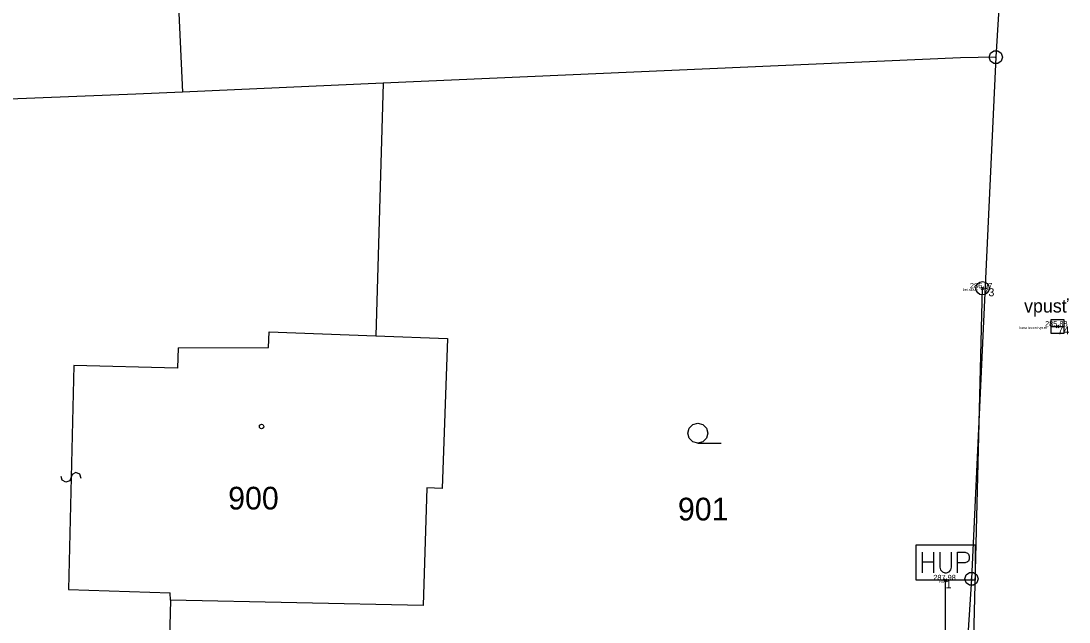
# Model space of a CAD drawing. Extents: x -456675 to -456278, y -1112395 to -1112217.
# Drawn here: x -456598.34 to -456559.06, y -1112289.23 to -1112266.7 of the extents above; entities that cross this region are included whole.
import ezdxf

# ---------------------------------------------------------------- set-up
doc = ezdxf.new("R2010")
doc.units = 0
for name, color, linetype in [('Cislo_bodu', 7, 'Continuous'), ('g_elektrina', 7, 'Continuous'), ('g_kanalizace', 7, 'Continuous'), ('g_ploty', 7, 'Continuous'), ('g_plyn', 7, 'Continuous'), ('Katastralni_mapa', 7, 'Continuous'), ('Kod_bodu', 7, 'Continuous'), ('Vyska_bodu', 7, 'Continuous'), ('Znacka_bodu', 7, 'Continuous')]:
    doc.layers.add(name, color=color, linetype=linetype)

msp = doc.modelspace()

# ---------------------------------------------------------------- linework, layer by layer
at = {"layer": 'g_elektrina'}
msp.add_lwpolyline([(-456563.36, -1112319.78), (-456562.97, -1112303.96), (-456562.3, -1112276.72)], dxfattribs=at)
msp.add_circle((-456562.3, -1112276.72), 0.25, dxfattribs=at)
at = {"layer": 'g_kanalizace'}
msp.add_line((-456559.74, -1112278.15), (-456559.24, -1112278.15), dxfattribs=at)
msp.add_lwpolyline([(-456559.74, -1112278.401), (-456559.24, -1112278.401), (-456559.24, -1112277.9), (-456559.74, -1112277.9)], close=True, dxfattribs=at)
at = {"layer": 'g_ploty'}
msp.add_lwpolyline([(-456588.66, -1112299.7), (-456577.12, -1112299.18), (-456570.18, -1112298.84), (-456563.86, -1112298.52), (-456563.69, -1112291.41), (-456563.68, -1112287.66)], dxfattribs=at)
at = {"layer": 'g_plyn'}
for points in [[(-456564.78, -1112286.34), (-456562.58, -1112286.34), (-456562.58, -1112287.66), (-456564.78, -1112287.66), (-456564.78, -1112286.34)], [(-456564.56, -1112286.615), (-456564.56, -1112287.385)], [(-456564.118, -1112287.385), (-456564.118, -1112286.615)], [(-456563.9, -1112286.615), (-456563.9, -1112287.167), (-456563.869, -1112287.275), (-456563.801, -1112287.348), (-456563.708, -1112287.385), (-456563.645, -1112287.385), (-456563.552, -1112287.348), (-456563.489, -1112287.275), (-456563.458, -1112287.167), (-456563.458, -1112286.615)], [(-456563.24, -1112286.615), (-456562.954, -1112286.615), (-456562.862, -1112286.652), (-456562.829, -1112286.688), (-456562.798, -1112286.76), (-456562.798, -1112286.87), (-456562.829, -1112286.943), (-456562.862, -1112286.978), (-456562.954, -1112287.015), (-456563.24, -1112287.015)], [(-456563.24, -1112287.385), (-456563.24, -1112286.615)], [(-456564.56, -1112286.978), (-456564.118, -1112286.978)]]:
    msp.add_lwpolyline(points, dxfattribs=at)
at = {"layer": 'Katastralni_mapa'}
for points in [[(-456593.5, -1112243.25), (-456592.28, -1112269.37)], [(-456560.44, -1112245.9), (-456561.8, -1112268.06)], [(-456563.13, -1112268.09), (-456584.77, -1112269.04)], [(-456561.8, -1112268.06), (-456563.13, -1112268.09)], [(-456561.8, -1112268.06), (-456562.71, -1112287.61)], [(-456561.825, -1112268.06), (-456561.775, -1112268.06)], [(-456584.77, -1112269.04), (-456592.28, -1112269.37)], [(-456584.77, -1112269.04), (-456585.04, -1112278.5)], [(-456594.03, -1112269.44), (-456608.25, -1112270.01)], [(-456592.28, -1112269.37), (-456594.03, -1112269.44)], [(-456589.06, -1112278.94), (-456589.04, -1112278.35)], [(-456589.04, -1112278.35), (-456585.04, -1112278.5)], [(-456585.04, -1112278.5), (-456582.35, -1112278.6)], [(-456592.45, -1112278.95), (-456592.47, -1112279.71)], [(-456592.45, -1112278.95), (-456589.06, -1112278.94)], [(-456582.35, -1112278.6), (-456582.55, -1112284.23)], [(-456596.36, -1112279.61), (-456596.56, -1112288.01)], [(-456592.47, -1112279.71), (-456596.36, -1112279.61)], [(-456572.966, -1112282.523), (-456573.156, -1112282.473), (-456573.291, -1112282.333), (-456573.341, -1112282.148), (-456573.291, -1112281.963), (-456573.156, -1112281.823), (-456572.966, -1112281.773), (-456572.776, -1112281.823), (-456572.641, -1112281.963), (-456572.591, -1112282.148), (-456572.641, -1112282.333), (-456572.776, -1112282.473), (-456572.966, -1112282.523), (-456572.091, -1112282.523)], [(-456596.086, -1112283.844), (-456596.132, -1112283.693), (-456596.286, -1112283.629), (-456596.422, -1112283.696), (-456596.513, -1112283.934), (-456596.654, -1112283.99), (-456596.798, -1112283.917), (-456596.834, -1112283.776)], [(-456583.13, -1112284.2), (-456583.27, -1112288.61)], [(-456582.55, -1112284.23), (-456583.13, -1112284.2)], [(-456562.71, -1112287.61), (-456563.42, -1112298.58)], [(-456562.735, -1112287.61), (-456562.685, -1112287.61)], [(-456596.56, -1112288.01), (-456592.75, -1112288.13)], [(-456592.74, -1112288.41), (-456592.75, -1112288.13)], [(-456592.74, -1112288.41), (-456593.04, -1112299.87)], [(-456583.27, -1112288.61), (-456592.74, -1112288.41)]]:
    msp.add_lwpolyline(points, dxfattribs=at)
for points in [[(-456561.725, -1112267.82), (-456561.6, -1112267.915), (-456561.55, -1112268.06), (-456561.6, -1112268.205), (-456561.725, -1112268.3), (-456561.875, -1112268.3), (-456562, -1112268.205), (-456562.05, -1112268.06), (-456562, -1112267.915), (-456561.875, -1112267.82)], [(-456589.32, -1112281.815), (-456589.27, -1112281.825), (-456589.245, -1112281.87), (-456589.235, -1112281.9), (-456589.245, -1112281.945), (-456589.285, -1112281.98), (-456589.32, -1112281.985), (-456589.365, -1112281.97), (-456589.395, -1112281.94), (-456589.405, -1112281.9), (-456589.395, -1112281.855), (-456589.355, -1112281.82)], [(-456562.635, -1112287.37), (-456562.51, -1112287.465), (-456562.46, -1112287.61), (-456562.51, -1112287.755), (-456562.635, -1112287.85), (-456562.785, -1112287.85), (-456562.91, -1112287.755), (-456562.96, -1112287.61), (-456562.91, -1112287.465), (-456562.785, -1112287.37)]]:
    msp.add_lwpolyline(points, close=True, dxfattribs=at)
at = {"layer": 'Znacka_bodu'}
for p, q in [((-456562.3, -1112276.72), (-456562.35, -1112276.67)), ((-456562.3, -1112276.72), (-456562.35, -1112276.77)), ((-456562.3, -1112276.72), (-456562.25, -1112276.67)), ((-456562.3, -1112276.72), (-456562.25, -1112276.77)), ((-456559.49, -1112278.15), (-456559.54, -1112278.1)), ((-456559.49, -1112278.15), (-456559.54, -1112278.2)), ((-456559.49, -1112278.15), (-456559.44, -1112278.1)), ((-456559.49, -1112278.15), (-456559.44, -1112278.2)), ((-456563.68, -1112287.66), (-456563.73, -1112287.61)), ((-456563.68, -1112287.66), (-456563.73, -1112287.71)), ((-456563.68, -1112287.66), (-456563.63, -1112287.61)), ((-456563.68, -1112287.66), (-456563.63, -1112287.71))]:
    msp.add_line(p, q, dxfattribs=at)

# ---------------------------------------------------------------- texts
at = {"layer": 'Cislo_bodu'}
for s, p in [('73', (-456562.3, -1112277.02)), ('74', (-456559.49, -1112278.45)), ('1', (-456563.68, -1112287.96))]:
    msp.add_text(s, height=0.3, dxfattribs=at).set_placement(p)
at = {"layer": 'g_kanalizace'}
msp.add_text('vpusť', height=0.5, dxfattribs=at).set_placement((-456560.741, -1112277.63))
at = {"layer": 'Katastralni_mapa'}
for s, p in [('900', (-456590.574, -1112285.01)), ('901', (-456573.716, -1112285.42))]:
    msp.add_text(s, height=0.85, dxfattribs=at).set_placement(p)
at = {"layer": 'Kod_bodu'}
for s, p in [('bet.sloup', (-456563.04, -1112276.82)), ('kanalizacni vpust', (-456560.921, -1112278.25)), ('HUP', (-456563.928, -1112287.76))]:
    msp.add_text(s, height=0.1, dxfattribs=at).set_placement(p)
at = {"layer": 'Vyska_bodu'}
for s, p in [('286.97', (-456562.771, -1112276.72)), ('285.88', (-456559.955, -1112278.15)), ('287.98', (-456564.145, -1112287.66))]:
    msp.add_text(s, height=0.2, dxfattribs=at).set_placement(p)

doc.saveas('drawing.dxf')
